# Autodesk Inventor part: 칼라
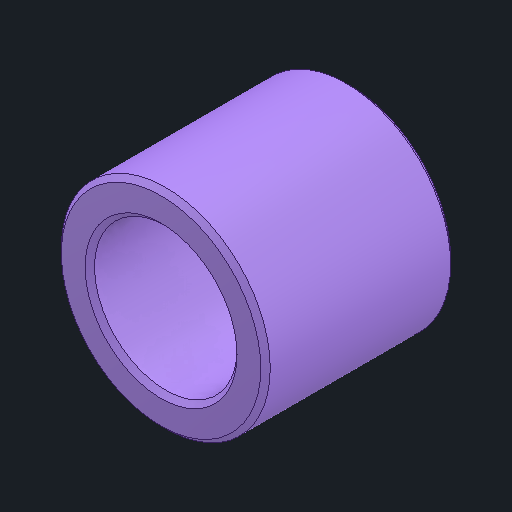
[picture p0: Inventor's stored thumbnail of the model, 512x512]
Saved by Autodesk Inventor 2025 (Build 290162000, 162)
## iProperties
Created: 2025-08
Part Number: 칼라
Material: 스테인리스강
Document SubType Name: Modeling
Designer: infra14
Density: 8.08 g/cm^3
Appearance: 기본값
Author: jhkim
Sending System: Autodesk Inventor 2026
Preprocessor: ST-DEVELOPER v20.1
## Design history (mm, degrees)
feature "솔리드1"
node "솔리드2"
